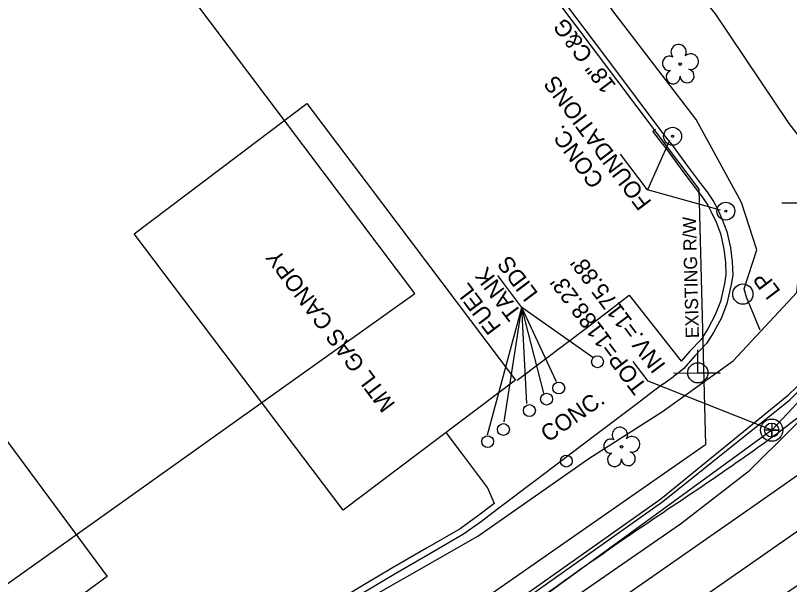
# Model space of a CAD drawing. Extents: x 1262092 to 1264624, y 774970 to 778314.
# Drawn here: x 1263058.9 to 1263246.8, y 776457.9 to 776596.1 of the extents above; entities that cross this region are included whole.
import ezdxf

# ---------------------------------------------------------------- set-up
doc = ezdxf.new("R2010")
doc.units = 0
for name, color, linetype in [('COGO Default Parcel', 7, 'Continuous'), ('Exist Horizontal Alignment', 7, 'Continuous'), ('Exist Horizontal Alignment Tick Small', 7, 'Continuous'), ('Exist Other Culture Gas Pump or Vent Leader', 7, 'Continuous'), ('Exist Other Culture Gas Pump or Vent Text', 7, 'Continuous'), ('Exist Right of Way Line', 7, 'Continuous'), ('Exist Right of Way Line Text', 7, 'Continuous'), ('Exist Roads Change in Surface Text', 7, 'Continuous'), ('Exist Roads Curbs', 7, 'Continuous'), ('Exist Roads EOP', 7, 'Continuous'), ('Exist Roads EOP Other', 7, 'Continuous'), ('Exist Roads EOT', 7, 'Continuous'), ('Exist Utilities Gas UG Line SUE LOS B', 7, 'Continuous'), ('Exist Utilities Other Located Object Leader', 7, 'Continuous'), ('Exist Utilities Other Located Object Text', 7, 'Continuous'), ('Exist Utilities Other Pole Text', 7, 'Continuous'), ('Exist Utilities Power Joint Use Telephone CELL', 7, 'Continuous'), ('Exist Utilities Power UG Cable SUE LOS B', 7, 'Continuous'), ('Exist Utilities Sanitary Sewer Manhole CELL', 7, 'Continuous'), ('Exist Utilities Sanitary Sewer Manhole Leader', 7, 'Continuous'), ('Exist Utilities Sanitary Sewer Manhole Text', 7, 'Continuous'), ('Exist Utilities Sanitary Sewer UG Line', 7, 'Continuous'), ('Exist Utilities Telephone UG FO SUE LOS B', 7, 'Continuous'), ('Prop EOT', 7, 'Continuous'), ('Prop Horizontal Alignment Direction Label', 7, 'Continuous'), ('Prop Horizontal Alignment Tick Label', 7, 'Continuous'), ('Prop Lane Lines', 7, 'Continuous'), ('Prop Shade Medium', 7, 'Continuous'), ('Prop Superelevation  Arrow CELL', 7, 'Continuous'), ('Sheet Sticker Incomplete CELL', 7, 'Continuous')]:
    doc.layers.add(name, color=color, linetype=linetype)

# ---------------------------------------------------------------- blocks, each defined once
blk = doc.blocks.new('EXIST UTILITIES SANITARY SEWER MANHOLE')
at = {"layer": 'Exist Utilities Sanitary Sewer Manhole CELL'}
blk.add_lwpolyline([(0, 0.03425), (0, -0.03425), (0, 0), (0.03425, 0), (-0.03425, 0)], dxfattribs=at)
for radius in [0.05389, 0.03425]:
    blk.add_circle((0, 0), radius, dxfattribs=at)

msp = doc.modelspace()

# ---------------------------------------------------------------- linework, layer by layer
at = {"layer": 'COGO Default Parcel'}
for p, q in [((1263155.86, 776528.63), (1262121.77, 777902.18)), ((1263013.38, 776427.15), (1263155.86, 776528.63))]:
    msp.add_line(p, q, dxfattribs=at)
at = {"layer": 'Exist Horizontal Alignment'}
msp.add_line((1263123.18, 776383.49), (1263698.47, 776784.16), dxfattribs=at)
at = {"layer": 'Exist Horizontal Alignment Tick Small'}
for p, q in [((1263220.28, 776584.31), (1263220.28, 776584.31)), ((1263206.01, 776491.4), (1263206.01, 776491.4))]:
    msp.add_line(p, q, dxfattribs=at)
for centre in [(1263220.28, 776584.31), (1263206.01, 776491.4)]:
    msp.add_circle(centre, 0.326, dxfattribs=at)
for centre, radius, start, end in [((1263219.89, 776587.19), 1.86, 330.1651, 219.7134), ((1263222.82, 776584.9), 1.9, 257.1011, 134.1999), ((1263217.67, 776584.47), 1.73, 62.6636, 279.3457), ((1263221.95, 776581.41), 1.7, 181.2822, 74.56), ((1263218.57, 776581.19), 1.69, 111.5671, 6.231), ((1263205.63, 776494.27), 1.86, 330.1651, 219.7134), ((1263203.41, 776491.55), 1.73, 62.6636, 279.3457), ((1263208.56, 776491.99), 1.9, 257.1011, 134.1999), ((1263204.31, 776488.28), 1.69, 111.5671, 6.231), ((1263207.69, 776488.5), 1.7, 181.2822, 74.56)]:
    msp.add_arc(centre, radius, start, end, dxfattribs=at)
at = {"layer": 'Exist Other Culture Gas Pump or Vent Leader'}
for p in [(1263173.49, 776494.27), (1263183.05, 776501.91), (1263187.2, 776504.43), (1263199.05, 776513.08)]:
    msp.add_line(p, (1263181.84, 776525.22), dxfattribs=at)
for points in [[(1263177.55, 776497.4), (1263181.84, 776525.22), (1263176.02, 776532.95)], [(1263190.27, 776507.12), (1263181.84, 776525.22)]]:
    msp.add_lwpolyline(points, dxfattribs=at)
at = {"layer": 'Exist Right of Way Line'}
for p, q in [((1262172.78, 777950.69), (1263224.83, 776553.94)), ((1263224.83, 776553.94), (1263226.42, 776491.95)), ((1263106.05, 776408.12), (1263226.42, 776491.95))]:
    msp.add_line(p, q, dxfattribs=at)
at = {"layer": 'Exist Roads Curbs'}
for points in [[(1263190.65, 776601.35), (1263202.86, 776585.11), (1263216.31, 776567.08), (1263218.32, 776564.58), (1263222.25, 776559.2), (1263225.23, 776555.28), (1263226.71, 776553.34), (1263228.36, 776550.9), (1263229.29, 776549.19), (1263230.49, 776546.6), (1263231.62, 776543.66), (1263232.51, 776539.65), (1263232.89, 776536.31), (1263233.04, 776533.07), (1263232.68, 776530.75), (1263231.61, 776526.15), (1263230.26, 776522.71), (1263228.38, 776519.16), (1263226.64, 776516.42), (1263223.83, 776513.48), (1263221.17, 776510.4), (1263219.04, 776508.7), (1263218.65, 776508.43)], [(1263216.03, 776506.6), (1263213.8, 776504.87), (1263209.23, 776501.42), (1263199.46, 776494.02), (1263185.09, 776483.09), (1263175.96, 776476.24), (1263172.02, 776473.25), (1263167.68, 776470.14), (1263159.5, 776465.39), (1263151.22, 776460.64), (1263143.62, 776456.08), (1263134.41, 776450.52), (1263125.08, 776444.97), (1263112.03, 776437.18), (1263102.92, 776431.9), (1263084.51, 776420.89), (1263074.17, 776414.6), (1263068.75, 776411.21), (1263059.14, 776404.65), (1263050.93, 776399.25)]]:
    msp.add_lwpolyline(points, dxfattribs=at)
at = {"layer": 'Exist Roads EOP'}
msp.add_spline([(1263270.33, 776616.29), (1263277.95, 776601.77), (1263283.55, 776577.66), (1263282.77, 776555.16), (1263273.97, 776526.11), (1263261.3, 776509.47), (1263242.63, 776493.72), (1263207.21, 776469.34), (1263177.26, 776448.17), (1263136.42, 776419.06), (1263111.74, 776401.16), (1263077.88, 776377.33), (1263049.63, 776356.49)], degree=3, dxfattribs=at)
at = {"layer": 'Exist Roads EOP Other'}
for p, q in [((1263213.6, 776567.95), (1263214.3, 776568.51)), ((1263216.03, 776506.6), (1263218.65, 776508.43))]:
    msp.add_line(p, q, dxfattribs=at)
for points in [[(1263213.6, 776567.95), (1263215.01, 776566.07), (1263217.01, 776563.57), (1263220.92, 776558.21), (1263223.91, 776554.28), (1263225.36, 776552.37), (1263226.95, 776550.04), (1263227.81, 776548.45), (1263228.97, 776545.95), (1263230.03, 776543.18), (1263230.88, 776539.38), (1263231.24, 776536.18), (1263231.38, 776533.16), (1263231.05, 776531.06), (1263230.03, 776526.64), (1263228.76, 776523.4), (1263226.95, 776519.99), (1263225.33, 776517.45), (1263222.6, 776514.59), (1263220.5, 776512.14)], [(1263175.16, 776477.62), (1263175, 776477.5), (1263171.08, 776474.52), (1263166.82, 776471.47), (1263158.71, 776466.76), (1263150.42, 776462), (1263142.8, 776457.43), (1263133.6, 776451.88), (1263124.27, 776446.33), (1263111.23, 776438.54), (1263102.12, 776433.26), (1263083.7, 776422.25), (1263073.34, 776415.94), (1263067.89, 776412.54), (1263058.26, 776405.96)]]:
    msp.add_lwpolyline(points, dxfattribs=at)
at = {"layer": 'Exist Roads EOT'}
msp.add_lwpolyline([(1263055.86, 776347.14), (1263093.56, 776375.13), (1263119.4, 776393.79), (1263119.03, 776393.52), (1263161.16, 776423.14), (1263194.13, 776446.35), (1263238.24, 776477.15), (1263266.32, 776496.83), (1263297.06, 776517.2), (1263326.49, 776538.85)], dxfattribs=at)
msp.add_spline([(1263237.98, 776450.36), (1263259.66, 776465.25), (1263288.73, 776485.12), (1263318.56, 776505.53), (1263341.21, 776520.98)], degree=3, dxfattribs=at)
at = {"layer": 'Exist Utilities Gas UG Line SUE LOS B'}
msp.add_circle((1263235.48, 776528.45), 2.46, dxfattribs=at)
at = {"layer": 'Exist Utilities Other Located Object Leader'}
msp.add_line((1263217.71, 776565.73), (1263212.3, 776553.79), dxfattribs=at)
msp.add_lwpolyline([(1263230.07, 776548.83), (1263212.3, 776553.79), (1263205.8, 776562.43)], dxfattribs=at)
at = {"layer": 'Exist Utilities Power Joint Use Telephone CELL'}
msp.add_line((1263224.56, 776509.33), (1263224.56, 776509.33), dxfattribs=at)
for points in [[(1263244.95, 776550.61), (1263256.28, 776550.57), (1263250.89, 776550.59), (1263250.89, 776556.23)], [(1263218.62, 776509.33), (1263229.96, 776509.29), (1263224.56, 776509.31), (1263224.56, 776514.95)]]:
    msp.add_lwpolyline(points, dxfattribs=at)
msp.add_circle((1263224.56, 776509.33), 2.45, dxfattribs=at)
at = {"layer": 'Exist Utilities Power UG Cable SUE LOS B'}
for points in [[(1263239.68, 776519.69), (1263236.4, 776527.69), (1263235.79, 776529.77), (1263238.91, 776539.16), (1263235.14, 776550.71), (1263224.14, 776570.85), (1263203.94, 776597.26), (1263189.25, 776618.77), (1263174.38, 776607.41), (1263177.5, 776602.49)], [(1263022.78, 776438.19), (1263051.86, 776397.67), (1263087, 776421.34), (1263109.96, 776436.23), (1263136.29, 776449.79), (1263136.3, 776449.76), (1263171.16, 776469.68), (1263198.08, 776488.52), (1263216, 776499.92), (1263233.17, 776512.29), (1263248.6, 776528.82), (1263250.89, 776550.61)]]:
    msp.add_lwpolyline(points, dxfattribs=at)
at = {"layer": 'Exist Utilities Sanitary Sewer Manhole Leader'}
msp.add_lwpolyline([(1263242.49, 776495.42), (1263212.5, 776507.31), (1263208.89, 776512.1)], dxfattribs=at)
at = {"layer": 'Exist Utilities Sanitary Sewer UG Line'}
for p, q in [((1263384.8, 776646.7), (1263242.49, 776495.42)), ((1263242.49, 776495.42), (1263052.88, 776357.28))]:
    msp.add_line(p, q, dxfattribs=at)
at = {"layer": 'Exist Utilities Telephone UG FO SUE LOS B'}
for points in [[(1263327.94, 776458.23), (1263319.84, 776479.77), (1263315.17, 776486.86), (1263298.56, 776508.1), (1263277.77, 776534.13), (1263266.99, 776547.03), (1263257.35, 776556.24), (1263246.76, 776569.88), (1263228.82, 776596.46), (1263216.74, 776611.46), (1263208.44, 776647.07), (1263209.78, 776666.55), (1263199.3, 776680.26), (1263169.29, 776716.69), (1263156.4, 776735.23), (1263140.27, 776757.21), (1263108.01, 776806.84), (1263086.96, 776838.9)], [(1263021.33, 776341.46), (1263058.42, 776367.65), (1263110.75, 776403.22), (1263171.15, 776446.27), (1263216.08, 776478.09), (1263246.91, 776502.79), (1263255.49, 776511.46), (1263262.4, 776520.59), (1263269.32, 776532.47), (1263272.46, 776540.67), (1263275.57, 776549.73), (1263276.9, 776560.75), (1263278.67, 776572.93), (1263277.86, 776582.26), (1263271.87, 776600.58)], [(1263024.86, 776334.48), (1263062.52, 776361.6), (1263114.14, 776398.23), (1263173.93, 776440.52), (1263220.36, 776472.64), (1263237.1, 776485.66), (1263257.13, 776505.55), (1263265.04, 776516.51), (1263272.71, 776529.97), (1263279.51, 776549.09), (1263281.5, 776560.23), (1263281.1, 776573), (1263279.91, 776583.04), (1263274.08, 776601.58)], [(1263021.72, 776341.54), (1263057.98, 776368.23), (1263110.45, 776403.76), (1263170.81, 776447.07), (1263215.57, 776478.73), (1263246.59, 776504.02), (1263255.25, 776512.33), (1263261.65, 776521.31), (1263268.82, 776532.91), (1263271.24, 776541.94), (1263272.91, 776550.27), (1263275.25, 776562.72), (1263276.67, 776572.87), (1263276.15, 776581.92), (1263270.16, 776599.83)]]:
    msp.add_lwpolyline(points, dxfattribs=at)
at = {"layer": 'Prop Horizontal Alignment Direction Label'}
msp.add_lwpolyline([(1263129.62, 776574.71), (1263180.3, 776507.59), (1263138.42, 776475.97), (1263087.74, 776543.09)], close=True, dxfattribs=at)
at = {"layer": 'Prop Horizontal Alignment Tick Label'}
for points in [[(1263180.72, 776507.55), (1263198.09, 776520.65), (1263207.9, 776528.16), (1263220.5, 776512.14)], [(1263175.16, 776477.62), (1263173.49, 776481.51), (1263167.17, 776489.93), (1263163.44, 776494.86)]]:
    msp.add_lwpolyline(points, dxfattribs=at)
at = {"layer": 'Prop Lane Lines'}
for centre, radius in [((1263218.44, 776566.76), 2.18), ((1263218.44, 776566.76), 0.24), ((1263231.35, 776548.59), 2.18), ((1263231.35, 776548.59), 0.24)]:
    msp.add_circle(centre, radius, dxfattribs=at)
at = {"layer": 'Prop Shade Medium'}
msp.add_lwpolyline([(1263081.14, 776459.88), (1263036.72, 776427.24), (1262997.83, 776480.18), (1262999.26, 776481.23), (1262996.83, 776484.5), (1262991.13, 776480.27), (1262983.97, 776489.92), (1262991.31, 776495.37), (1262966.61, 776528.65), (1263006.2, 776558.04), (1263044.1, 776507), (1263045.49, 776508.05)], close=True, dxfattribs=at)
at = {"layer": 'Prop Superelevation  Arrow CELL'}
for centre in [(1263200.2, 776512.02), (1263190.8, 776505.64), (1263187.84, 776502.95), (1263183.67, 776500.17), (1263177.37, 776495.57), (1263173.53, 776492.64), (1263192.63, 776487.9)]:
    msp.add_circle(centre, 1.44, dxfattribs=at)

# ---------------------------------------------------------------- block references
at = {"layer": 'Exist Utilities Sanitary Sewer Manhole CELL', "xscale": 50, "yscale": 50}
msp.add_blockref('EXIST UTILITIES SANITARY SEWER MANHOLE', (1263242.49, 776495.42), dxfattribs=at)
msp.add_blockref('EXIST UTILITIES SANITARY SEWER MANHOLE', (1263242.49, 776495.42), dxfattribs=at)

# ---------------------------------------------------------------- texts
at = {"layer": 'Exist Other Culture Gas Pump or Vent Text'}
for s, p in [('LIDS', (1263185.94, 776528.62)), ('TANK ', (1263181.96, 776523.93)), ('FUEL', (1263177, 776520.55))]:
    msp.add_text(s, height=4, rotation=126.9874, dxfattribs=at).set_placement(p)
at = {"layer": 'Exist Right of Way Line Text'}
msp.add_text('EXISTING R/W', height=3.2, rotation=91.4743, dxfattribs=at).set_placement((1263224.83, 776517.78))
at = {"layer": 'Exist Roads Change in Surface Text'}
msp.add_text('CONC.', height=4, rotation=34.8555, dxfattribs=at).set_placement((1263188.18, 776492.32))
at = {"layer": 'Exist Utilities Other Located Object Text'}
for s, p in [('FOUNDATIONS', (1263213.48, 776550.78)), ('CONC.', (1263201.98, 776556.08))]:
    msp.add_text(s, height=4, rotation=126.9874, dxfattribs=at).set_placement(p)
at = {"layer": 'Exist Utilities Other Pole Text'}
msp.add_text('LP', height=4, rotation=126.9874, dxfattribs=at).set_placement((1263244.8, 776529.12))
at = {"layer": 'Exist Utilities Sanitary Sewer Manhole Text'}
for s, p in [("INV.=1175.88'", (1263216.95, 776511.21)), ("TOP=1188.23'", (1263212.39, 776506.04))]:
    msp.add_text(s, height=4, rotation=126.9874, dxfattribs=at).set_placement(p)
at = {"layer": 'Prop EOT'}
msp.add_text('MTL GAS CANOPY', height=4, rotation=126.9874, dxfattribs=at).set_placement((1263151.25, 776501.71))
at = {"layer": 'Sheet Sticker Incomplete CELL'}
msp.add_text('18" C&G', height=4, rotation=126.9368, dxfattribs=at).set_placement((1263204.87, 776579.11))

doc.saveas('drawing.dxf')
